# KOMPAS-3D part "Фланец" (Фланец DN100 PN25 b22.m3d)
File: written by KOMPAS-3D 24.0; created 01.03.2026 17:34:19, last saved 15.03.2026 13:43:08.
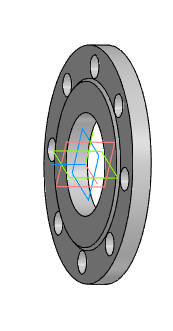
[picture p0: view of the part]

Document properties: Автор: R2D2; Полное имя файла: E:\Работа\Зайцев\GVWR2434M-2W-F-ОСТ Задвижка клиновая с выдвижным штоком DN.ru Ду50-300 Ру25\исходные материалы\DN100\Фланец DN100 PN25 b22.m3d

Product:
- Part/product: Фланец
    Масса: 4.839866
    additional columns: Типовые

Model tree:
1. Эскиз:2
2. Элемент вращения:1
     Угол 1 = 360
3. Эскиз:3  (with: Грань.Элемент вращения:1)
4. Элемент выдавливания:2
     Расстояние 1 = 50
5. Массив по концентрической сетке:1  (with: Элемент выдавливания:2, Эскиз:3, Грань.Элемент вращения:1)  (8 pattern instances)
     Шаг 2 = 360
6. Эскиз:4  (with: Грань.Элемент вращения:1)
7. Элемент выдавливания:3
     Расстояние 2 = 3

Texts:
  Линейный размер с обрывом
